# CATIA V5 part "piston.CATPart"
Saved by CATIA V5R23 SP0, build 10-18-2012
Part number: piston
Definition: piston
Source: made
Bounding box of the stored display mesh (mm): x -58 to 0, y -24.951 to 24.951, z -25 to 25
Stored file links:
  C:\wamp\www\COURS\CONCEPTION GMP1\TITRE 01-CATIA VOLUMIQUE\05--ACTIONNEUR DE VANNE\prof\CORRECTION\Assemblage\piston.CATPart
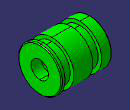
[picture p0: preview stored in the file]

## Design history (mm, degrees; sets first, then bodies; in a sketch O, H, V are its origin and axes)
Set1
  Point1 "Point.1": type Center, Curve edge [face of Solid1 | face of Solid1]
Body1 "NONE" (main body)
  Solid1 "Manifold Solid #2275": solid without history
  Sketch1 on face of Solid1, origin (-58, -15.3638, 9.3711), H (0, 1, 0), V (0, 0, -1)
    point P1 (15.3638, -6.6289)
    construction line L1 (59.5919, 9.3711) -> (-17.1036, 9.3711)
    axis line L2 (15.3638, 29.5864) -> (15.3638, -11.6665)
    reference projected point E1 (15.3638, 9.3711) from Point1
    reference projected point E4 (15.3638, 9.3711) from Point1
    distance L1 P1 = 16
    horizontal: L1 H
    vertical: L2 V
    coincidence: L2 E1, E4 L1, P1 L2
  Hole1: placed by Sketch1, at (-58, 0, 16) direction (1, 0, 0), diameter 4, depth 10, V-bottom angle 120
  CircPattern1: of Hole1, instances 4, angular step 90 {= 360.0*1 deg/CircPattern1.AngularNumber}, axis from face of Solid1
